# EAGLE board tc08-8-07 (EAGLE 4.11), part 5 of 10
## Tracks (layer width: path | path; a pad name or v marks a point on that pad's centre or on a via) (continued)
I/O_BAC_06  (via drill 0.61) (continued)
  Bottom 0.254: v354.37,76.5 349.29,76.5 348.97,76.82 348.33,76.82 348.02,76.5 v339.13,76.5 | v337.86,101.27 335.63,101.27 C03.R1 334.36,101.91 v330.87,101.91 | v344.52,233.99 v344.52,235.89 | v337.86,216.21 337.54,216.52 334.68,216.52 v334.36,216.84
I/O_BAC_07  (via drill 0.61)
  Top 0.254: D02.P1 350.56,35.55 350.56,39.68 349.6,40.63 349.6,46.34 348.97,46.98 348.97,54.92 349.29,55.23 349.29,73.33 350.87,74.92 v350.87,86.98 350.56,87.3 350.56,89.84 349.29,91.11 349.29,104.44 348.97,104.76 348.97,137.46 349.29,137.78 349.29,152.71 348.65,153.34 348.65,156.2 349.29,156.83 349.29,162.55 348.97,162.86 348.97,169.21 349.29,169.53 349.29,173.98 348.97,174.3 348.97,206.36 350.87,208.27 350.87,223.51 349.6,224.78 349.6,232.4 349.92,232.71 349.92,236.84 350.56,237.48 A02.P1
  Bottom 0.254: v350.87,86.98 337.22,86.98 335.63,88.57 C03.V1
I/O_BAC_08  (via drill 0.61)
  Top 0.254: v348.65,46.03 348.97,45.71 348.97,40.31 349.29,39.99 349.29,30.47 350.56,29.2 D02.S1 | v352.78,47.29 352.46,47.61 352.46,48.25 349.6,51.1 349.6,54.6 350.24,55.23 350.24,57.77 352.14,59.68 352.14,62.53 351.51,63.17 351.51,64.44 v354.37,67.3 | v353.41,231.45 352.78,230.81 352.78,225.09 v353.1,224.78 | v352.78,195.57 354.68,193.66 354.68,191.76 355.32,191.12 355.32,188.27 v354.68,187.63 | v363.89,185.73 362.3,184.14 362.3,166.68 364.21,164.77 v364.21,163.5
  Route2 0.254: v358.81,73.33 358.81,73.97 361.03,76.19 361.03,78.09 361.67,78.73 361.67,79.68 361.99,80 361.99,83.17 v363.57,84.76 | v353.1,224.78 353.1,224.14 352.14,223.19 352.14,218.11 350.87,216.84 350.87,208.27 349.6,207 349.6,205.73 354.37,200.96 352.46,199.06 352.46,195.89 v352.78,195.57 | v364.21,163.5 366.75,160.96 v345.16,139.37
  Route15 0.254: v364.21,94.6 361.67,97.14 361.67,97.78 356.59,102.86 356.59,103.49 333.73,126.35 333.73,127.94 332.14,129.53 C03.E2 332.14,130.8 333.09,131.75 333.09,132.39 332.46,133.02 337.54,138.1 v337.54,139.05 | v354.68,187.63 355,187.63 356.91,185.73 v360.08,185.73
  Bottom 0.254: v348.65,46.03 351.19,46.03 352.46,47.29 v352.78,47.29 | v354.37,67.3 356.27,65.39 357.86,65.39 359.45,66.98 359.45,68.88 358.81,69.52 v358.81,73.33 | v363.57,84.76 363.57,89.52 364.53,89.52 365.16,90.16 365.16,94.6 v364.21,94.6 | v353.41,231.45 351.51,231.45 A02.S1 | v363.89,185.73 v360.08,185.73 | v345.16,139.37 343.57,140.96 340.71,140.96 338.81,139.05 v337.54,139.05
I/O_BAC_09  (via drill 0.61)
  Top 0.254: v362.62,65.08 362.3,65.39 362.3,77.46 | 362.3,77.46 362.3,79.36 362.62,79.68 362.62,85.39 362.94,85.71 362.94,90.79 361.99,91.74 361.99,97.14 361.67,97.46 361.67,126.03 v361.99,126.35 | v332.14,126.03 332.14,124.45 C03.H2 | v348.97,265.1 v346.75,265.1 | v362.62,77.46 362.3,77.46
  Route2 0.254: v372.78,240.97 371.83,240.02 371.83,225.09 373.42,223.51 373.42,148.26 371.83,146.67 371.83,145.72 371.51,145.4 371.51,106.67 373.42,104.76 373.42,73.01 v371.83,71.43
  Bottom 0.254: v362.62,65.08 360.08,65.08 357.22,62.22 342.94,62.22 341.98,63.17 D02.D2 | v361.99,126.35 361.35,125.72 332.46,125.72 v332.14,126.03 | v346.75,265.1 346.43,265.42 342.94,265.42 341.98,266.37 A02.D2 | v348.97,265.1 358.49,265.1 361.03,262.56 362.62,262.56 363.26,261.93 366.43,261.93 366.75,262.24 367.38,262.24 371.83,257.8 371.83,240.97 v372.78,240.97 | v371.83,71.43 371.83,79.36 363.26,79.36 362.62,78.73 v362.62,77.46
I/O_BAC_10  (via drill 0.61)
  Top 0.254: v321.66,116.83 321.66,115.56 321.03,114.92 321.03,105.08 321.66,104.44 321.66,102.86 321.03,102.22 321.03,98.1 321.66,97.46 321.66,96.51 320.39,95.24 320.39,90.47 319.44,89.52 319.44,84.76 317.54,82.86 v317.54,76.5 | v321.03,59.04 v321.03,75.87 | v348.02,256.53 348.02,256.85 345.16,259.7 345.16,262.56 344.84,262.88 A02.E2 | v349.92,254.62 349.6,254.3 349.6,251.45 349.29,251.13 349.29,249.86 351.51,247.64 v351.51,246.68
  Route2 0.254: v349.92,254.62 v348.02,256.53 | v370.56,210.49 370.56,170.49 372.15,168.9 372.15,150.48 370.56,148.89 370.56,147.94 370.24,147.62 370.24,64.76 363.26,57.77 363.26,57.14 v362.62,56.5
  Route15 0.254: v351.51,246.68 351.51,245.73 355.32,241.92 355.32,229.22 361.67,222.87 361.67,219.38 362.62,218.43 362.62,217.79 369.61,210.81 370.24,210.81 v370.56,210.49
  Bottom 0.254: v321.66,116.83 322.3,116.19 330.24,116.19 331.19,117.14 C03.K2 | v317.54,76.5 318.17,75.87 v321.03,75.87 | v321.03,59.04 342.94,59.04 343.89,60 D02.E2 345.16,60 346.75,60 350.87,55.87 361.99,55.87 v362.62,56.5
I/O_BAC_11  (via drill 0.61)
  Top 0.254: v323.89,110.48 323.57,110.16 323.57,95.87 324.2,95.24 324.2,90.47 326.11,88.57 v326.11,84.76 | v360.72,86.03 361.99,84.76 361.99,80 361.67,79.68 v361.67,53.33 | v292.77,273.67 292.45,273.99 292.45,288.28 290.87,289.86 290.87,296.85 333.41,296.85 340.71,289.55 340.71,286.05 342.62,284.15 342.62,263.51 343.57,262.56 343.57,258.43 344.21,257.8 A02.H2 | v284.52,271.13 283.56,270.18 283.56,267.96 282.93,267.32 282.93,251.45 v283.25,251.13 | v264.83,250.18 263.88,249.23 263.88,245.73 264.51,245.1 264.51,242.56 263.24,241.29 v263.24,219.38 | v91.79,219.06 92.11,218.74 92.11,204.46 88.62,200.96 88.62,196.2 87.35,194.93 v87.35,193.34 | v85.76,189.85 85.44,189.54 85.44,158.1 85.13,157.79 85.13,156.52 85.44,156.2 85.44,35.55 92.11,28.88 v92.11,27.61 | v149.26,28.25 149.58,28.56 149.58,32.37 150.21,33.01 152.75,33.01 152.75,32.37 159.1,26.02 159.1,21.58 163.55,17.13 178.47,17.13 v178.47,19.35 | v181.96,22.85 v185.46,19.35 | v193.08,19.35 v196.25,22.53
  Route2 0.254: v143.86,27.29 145.13,27.29 146.72,25.71 v149.26,28.25 | v178.47,19.35 v181.96,22.85 | v254.99,10.46 262.61,2.84 262.93,3.16 290.87,3.16 291.5,3.8 292.45,3.8 341.03,52.38 342.62,52.38 343.89,53.64 D02.H2
  Route15 0.254: v277.85,255.58 276.9,255.58 v271.82,250.49 | v196.25,22.53 198.47,24.75 204.19,19.04 204.19,18.4 204.82,17.77 206.41,17.77 207.05,17.13 208,17.13 209.27,15.86 211.17,15.86 211.81,15.23 216.25,15.23 219.43,12.05 221.02,12.05 221.65,11.42 233.72,11.42 v234.03,11.1
  Bottom 0.254: v323.89,110.48 324.52,109.84 330.24,109.84 331.19,110.8 C03.M2 | v326.11,84.76 326.43,85.08 335.95,85.08 336.59,85.71 349.92,85.71 350.24,85.39 353.1,85.39 353.73,86.03 v360.72,86.03 | v361.67,53.33 361.03,52.69 349.6,52.69 348.65,53.64 345.16,53.64 D02.H2 | v292.77,273.67 292.77,272.4 291.82,272.4 290.55,271.13 v284.52,271.13 | v283.25,251.13 278.8,255.58 v277.85,255.58 | v271.82,250.49 270.86,249.54 265.47,249.54 v264.83,250.18 | v263.24,219.38 200.06,219.38 199.74,219.06 v91.79,219.06 | v87.35,193.34 85.76,191.76 v85.76,189.85 | v92.11,27.61 93.06,26.66 143.23,26.66 v143.86,27.29 | v185.46,19.35 187.04,17.77 191.49,17.77 v193.08,19.35 | v234.03,11.1 234.99,10.15 254.67,10.15 v254.99,10.46
I/O_BMB_00  (via drill 0.61)
  Top 0.254: v335.32,65.39 335.32,69.2 D03.B1 | v310.55,61.27 311.19,60.63 311.19,22.53 305.79,17.13 v305.79,12.05 | v112.43,11.42 110.84,13.01 110.84,172.39 v110.53,172.71 | v134.34,173.02 133.7,173.66 133.7,293.68 134.34,294.31 v134.34,294.94 | v232.13,296.22 236.89,291.45 v236.89,286.05 | v328.65,281.93 334.68,275.9 334.68,273.67 A03.B1 | v351.83,153.98 351.83,144.13 351.19,143.5 C02.A1 | v362.94,153.98 362.3,154.61 362.3,157.79 362.62,158.1 362.62,160.96 362.3,161.28 362.3,163.5 v362.94,164.14 | v360.4,207.63 v360.4,210.17 | v361.03,217.79 359.13,219.7 359.13,227.95 358.81,228.27 358.81,240.02 358.49,240.33 358.49,247.32 358.81,247.64 358.81,249.54 359.45,250.18 359.45,253.04 358.81,253.67 v358.81,277.8
  Bottom 0.254: v335.32,65.39 336.27,64.44 336.27,62.22 313.73,62.22 312.77,63.17 311.19,63.17 310.55,62.53 v310.55,61.27 | v305.79,12.05 305.47,12.37 292.77,12.37 292.14,11.74 272.45,11.74 272.13,11.42 257.85,11.42 255.94,9.51 234.35,9.51 232.45,11.42 221.33,11.42 220.7,10.78 115.29,10.78 114.65,11.42 v112.43,11.42 | v110.53,172.71 134.02,172.71 v134.34,173.02 | v134.34,294.94 134.66,294.63 145.45,294.63 145.77,294.31 173.07,294.31 173.71,294.94 203.87,294.94 204.19,294.63 205.46,294.63 207.68,296.85 231.49,296.85 v232.13,296.22 | v236.89,286.05 238.8,284.15 238.8,283.83 240.38,282.24 270.23,282.24 271.18,283.2 299.44,283.2 301.03,281.61 328.33,281.61 v328.65,281.93 354.68,281.93 v358.81,277.8 | v362.94,153.98 v351.83,153.98 | v362.94,164.14 368.02,169.21 368.02,205.09 362.94,205.09 v360.4,207.63 | v360.4,210.17 360.4,210.81 361.99,212.39 361.99,217.79 v361.03,217.79
I/O_BMB_01  (via drill 0.61)
  Top 0.254: v329.6,65.08 329.28,65.39 v329.28,68.25 | v331.19,70.16 333.09,72.06 v333.09,77.14 | v352.46,77.46 353.41,76.5 v353.41,73.97 | v357.86,71.43 360.08,71.43 v360.08,76.5 | v360.72,131.43 359.76,131.43 359.76,132.07 358.81,133.02 v358.81,140.32 | v348.33,138.1 348.02,137.78 348.02,133.97 C02.D1 | v346.75,263.19 349.6,260.34 349.6,256.53 v351.51,254.62 | v364.21,241.61 362.62,240.02 362.62,239.06 362.3,238.75 362.3,237.48 363.26,236.52 v363.89,236.52 | v365.48,197.47 365.8,197.15 365.8,192.08 v364.84,191.12
  Route2 0.254: v365.16,248.27 365.16,242.56 v364.21,241.61
  Route15 0.254: v364.21,108.25 364.21,108.57 362.3,110.48 362.3,113.02 v363.26,113.97 | v363.89,236.52 363.89,235.26 364.84,234.3 364.84,223.83 365.16,223.51 365.16,217.79 370.88,212.08 370.88,211.44 371.51,210.81 371.51,203.51 v365.48,197.47 | v364.84,191.12 364.84,184.46 365.16,184.14 365.16,182.23 365.48,181.92 365.48,164.45 365.8,164.14 365.8,151.43 367.38,149.85 367.38,138.1 v360.72,131.43
  Bottom 0.254: v329.6,65.08 333.09,65.08 334.36,63.81 D03.D1 | v331.19,70.16 v329.28,68.25 | v333.09,77.14 333.41,77.46 344.84,77.46 345.16,77.14 347.7,77.14 348.02,77.46 v352.46,77.46 | v353.41,73.97 355.95,71.43 v357.86,71.43 | v360.08,76.5 360.08,77.14 369.29,86.35 369.29,108.25 v364.21,108.25 | v363.26,113.97 364.53,115.24 365.16,115.24 368.97,119.05 368.97,131.43 v360.72,131.43 | v358.81,140.32 358.18,140.96 351.51,140.96 348.65,138.1 v348.33,138.1 | v346.75,263.19 345.16,264.78 341.35,264.78 340.4,265.74 336.27,265.74 335.63,266.37 A03.D1 | v351.51,254.62 353.73,252.4 357.54,252.4 358.81,251.13 358.81,246.37 359.76,246.37 360.08,246.05 362.3,246.05 364.53,248.27 v365.16,248.27
I/O_BMB_02  (via drill 0.61)
  Top 0.254: v339.13,65.08 338.17,64.12 D03.E1 | v353.1,96.83 354.05,97.78 354.05,99.68 352.78,100.95 352.78,102.22 353.41,102.86 v353.41,105.08 | v337.86,266.69 337.86,264.15 A03.E1 | v314.36,270.81 v314.36,266.37 | v303.88,271.13 302.61,269.86 302.61,268.91 v301.03,267.32 | v289.91,263.19 288.96,262.24 288.96,259.38 v289.28,259.07
  Route2 0.254: v339.13,65.08 339.13,65.71 339.76,66.35 339.76,70.79 341.03,72.06 341.03,80.63 341.35,80.95 341.35,85.08 344.21,87.94 | 344.21,87.94 v353.1,96.83 | v347.06,111.75 353.1,117.78 353.73,117.78 v354.37,118.41 | v289.28,259.07 289.28,255.89 287.06,253.67 287.06,252.4 v274.67,240.02 | v268.96,241.29 267.69,241.29 242.61,216.21 241.34,216.21 238.16,213.03 238.16,206.36 237.84,206.05 237.84,205.41 234.99,202.55 234.99,201.28 234.67,200.96 234.67,195.57 232.45,193.34 232.45,192.71 229.59,189.85 229.59,188.58 228.95,187.95 228.95,184.77 228.64,184.46 228.64,183.82 227.05,182.23 226.73,182.23 225.14,180.64 225.14,180.33 223.24,178.42 223.24,177.15 v222.29,176.2 | v259.12,129.53 259.12,131.43 261.34,133.65 261.97,133.65 264.51,131.11 264.51,130.48 v264.2,130.16 | v324.2,88.89 329.28,83.81 333.09,87.62 338.17,87.62 340.71,90.16 341.98,90.16 344.21,87.94
  Route15 0.254: v353.41,105.08 353.41,105.4 v347.06,111.75 | v354.37,118.41 349.6,123.18 349.6,124.77 348.02,126.35 C02.F1 | v219.75,174.3 217.84,172.39 220.06,170.17 220.7,170.17 221.97,168.9 221.97,166.68 222.6,166.04 222.6,164.77 224.19,163.18 224.51,163.18 225.14,162.55 225.14,157.47 228,154.61 229.27,154.61 229.59,154.29 234.35,154.29 241.65,146.99 243.24,146.99 250.54,139.69 250.54,138.42 259.12,129.84 v259.12,129.53 | v264.2,130.16 264.2,129.84 266.42,127.62 266.42,125.08 265.15,123.81 v270.23,118.73 | v274.67,119.69 276.26,119.69 288.33,107.62 288.33,105.72 288.64,105.4 288.64,101.59 v297.85,92.38 | v306.11,90.47 306.74,90.47 314.68,98.41 v324.2,88.89
  Bottom 0.254: v337.86,266.69 336.59,267.96 321.35,267.96 318.81,265.42 315.31,265.42 v314.36,266.37 | v314.36,270.81 311.19,273.99 310.55,273.99 309.92,274.62 307.69,274.62 304.2,271.13 v303.88,271.13 | v301.03,267.32 298.49,264.78 291.5,264.78 v289.91,263.19 | v274.67,240.02 270.23,240.02 v268.96,241.29 | v222.29,176.2 220.38,174.3 v219.75,174.3 | v270.23,118.73 270.86,119.37 274.36,119.37 v274.67,119.69 | v297.85,92.38 300.07,90.16 305.79,90.16 v306.11,90.47
I/O_BMB_03  (via drill 0.61)
  Top 0.254: 334.68,115.88 v335.32,116.51 | 334.68,115.88 333.41,114.61 333.41,88.57 334.36,87.62 334.36,72.38 333.41,71.43 333.41,56.82 334.36,55.87 334.36,51.74 334.68,51.42 D03.J1 | 333.41,132.07 333.41,123.81 333.09,123.49 333.09,117.46 334.68,115.88 | 333.41,132.07 333.41,154.29 333.09,154.61 333.09,179.06 333.41,179.37 333.41,203.51 335,205.09 335,214.93 333.41,216.52 333.41,238.43 332.78,239.06 332.78,241.92 333.09,242.24 333.09,251.77 334.68,253.35 A03.J1 | 333.41,132.07 v330.87,132.07
  Bottom 0.254: C05.D2 303.88,133.65 304.2,133.97 308.33,133.97 308.96,134.61 311.19,134.61 312.14,133.65 315.31,133.65 C04.D2 316.58,133.02 317.54,132.07 322.93,132.07 323.25,132.39 327.7,132.39 328.01,132.07 v330.87,132.07 | v335.32,116.51 337.86,119.05 342.94,119.05 344.21,120.32 347.06,120.32 C02.J1
I/O_BMB_03\  (via drill 0.61)
  Top 0.254: v339.13,62.53 339.44,62.22 339.44,59.68 339.13,59.36 339.13,55.23 338.49,54.6 D03.H1 | v339.13,267.32 339.44,267 339.44,261.29 338.49,260.34 338.49,257.8 A03.H1
  Route15 0.254: v354.37,66.03 355.95,66.03 356.59,65.39 358.81,65.39 360.72,67.3 361.03,67.3 373.42,79.68 373.42,115.24 v372.46,116.19 | v372.46,145.08 372.46,145.4 371.83,146.04 371.83,148.26 373.42,149.85 373.42,237.8 371.83,239.38 371.83,241.29 v372.78,242.24
  Bottom 0.254: v339.13,62.53 339.13,64.12 340.08,64.12 341.03,65.08 351.83,65.08 352.78,66.03 v354.37,66.03 | v372.46,145.08 v372.46,116.19 | v372.78,242.24 372.78,265.1 359.45,265.1 356.91,267.64 355,267.64 354.68,267.96 351.83,267.96 351.51,267.64 348.65,267.64 348.33,267.96 345.48,267.96 345.16,267.64 342.3,267.64 341.98,267.96 339.76,267.96 v339.13,267.32
I/O_BMB_04  (via drill 0.61)
  Top 0.254: v364.84,42.53 365.16,42.85 365.16,74.28 364.84,74.6 364.84,76.5 365.16,76.82 365.16,112.07 v364.84,112.38 | v366.75,242.56 366.43,242.24 366.43,203.19 367.38,202.24 367.38,201.6 367.07,201.28 367.07,145.4 366.43,144.77 366.43,113.33 v366.75,113.02 | v320.71,115.88 320.39,116.19 320.39,128.58 319.44,129.53 C04.E2
  Bottom 0.254: C05.E2 307.06,130.48 307.38,130.8 311.5,130.8 312.14,131.43 316.27,131.43 317.22,130.48 318.49,130.48 C04.E2 | v364.84,42.53 343.89,42.53 343.57,42.21 339.44,42.21 338.81,41.58 D03.M1 | v366.75,242.56 362.62,242.56 362.3,242.87 340.08,242.87 338.81,244.14 A03.M1 | v366.75,113.02 366.43,112.7 365.16,112.7 v364.84,112.38 352.14,112.38 350.56,113.97 348.33,113.97 C02.L1 347.7,114.92 346.11,116.51 345.48,116.51 345.16,116.19 336.27,116.19 335.63,115.56 321.03,115.56 v320.71,115.88
I/O_BMB_04\  (via drill 0.61)
  Top 0.254: v306.11,254.94 307.69,256.53 v307.69,261.93 | v331.19,258.75 333.09,258.75 333.09,254.62 v332.78,254.3 | v337.54,253.35 336.59,252.4 336.59,249.54 337.22,248.91 v337.22,247.96
  Route2 0.254: v283.88,73.65 283.88,73.97 284.83,74.92 284.83,78.73 281.34,82.22 281.66,82.54 281.66,90.79 282.29,91.43 282.29,95.24 288.33,101.27 288.33,103.81 291.82,107.3 291.82,109.84 292.14,110.16 292.14,119.37 299.76,126.99 v299.76,127.3 | v287.69,157.15 291.5,157.15 v296.26,161.91 | v285.15,186.04 288.01,186.04 298.17,196.2 298.17,207.63 284.83,220.97 285.47,221.6 285.47,225.41 v287.37,227.32
  Route15 0.254: v332.14,46.03 333.41,44.75 334.36,44.75 D03.L1 | v306.11,46.03 303.57,46.03 287.37,62.22 287.06,62.22 286.42,62.85 286.42,64.44 284.83,66.03 284.83,67.3 282.93,69.2 282.93,72.69 v283.88,73.65 | v299.76,127.3 292.77,134.29 292.77,135.56 292.14,136.2 292.14,145.72 289.28,148.58 289.28,150.17 287.37,152.07 287.37,153.66 286.1,154.93 286.1,156.2 287.37,157.47 v287.69,157.15 | v296.26,161.91 296.26,163.82 292.45,167.63 292.45,168.26 291.18,169.53 290.55,169.53 289.28,170.8 289.28,182.55 287.06,184.77 286.42,184.77 v285.15,186.04 | v287.69,230.18 289.6,232.08 289.28,232.4 289.28,233.35 v287.37,235.26 | v304.52,249.54 304.52,253.35 v306.11,254.94
  Bottom 0.254: v332.14,46.03 333.09,46.98 333.09,49.2 327.7,49.2 326.74,50.15 326.11,50.15 319.76,43.8 317.22,43.8 316.27,42.85 314.04,42.85 310.87,46.03 v306.11,46.03 | v287.37,227.32 287.37,230.18 v287.69,230.18 | v287.37,235.26 296.26,244.14 296.58,244.14 299.12,246.68 299.12,248.59 302.3,248.59 303.25,249.54 v304.52,249.54 | v307.69,261.93 312.46,261.93 315.63,258.75 v331.19,258.75 | v332.78,254.3 334.36,252.72 335.63,252.72 336.27,253.35 v337.54,253.35 | v337.22,247.96 335.63,247.96 A03.L1
I/O_BMB_05  (via drill 0.61)
  Top 0.254: v363.26,30.15 365.8,32.69 365.8,60.31 367.07,61.58 367.07,62.22 366.43,62.85 366.43,73.33 367.38,74.28 367.38,75.55 367.07,75.87 367.07,99.05 367.7,99.68 v367.7,106.35 368.02,106.67 368.02,109.52 368.34,109.84 368.34,122.22 367.7,122.86 367.7,125.08 | v368.02,227.95 367.7,227.64 367.7,203.82 368.65,202.87 368.65,200.96 368.34,200.65 368.34,144.77 367.7,144.13 367.7,125.08 | 367.7,125.08 v368.02,125.08 | v315.95,124.77 C04.F2
  Bottom 0.254: C05.F2 306.74,126.99 308.01,128.26 314.36,128.26 315.31,127.3 C04.F2 | v363.26,30.15 344.21,30.15 343.57,29.51 339.44,29.51 338.81,28.88 D03.S1 | v367.7,106.35 367.38,106.03 352.14,106.03 350.56,107.62 348.33,107.62 C02.N1 | v368.02,227.95 365.48,230.49 339.76,230.49 338.81,231.45 A03.S1 | v315.95,124.77 316.27,125.08 v368.02,125.08
I/O_BMB_05\
  Top 0.254: D03.P1 337.86,35.55 336.9,36.5 336.9,46.98 336.59,47.29 336.59,48.88 336.9,49.2 336.9,66.03 336.59,66.35 336.59,81.27 336.27,81.58 336.27,87.3 336.9,87.94 336.9,132.07 336.59,132.39 336.59,179.37 336.27,179.69 336.27,218.74 336.9,219.38 336.9,236.52 337.86,237.48 A03.P1
I/O_BMB_06  (via drill 0.61)
  Top 0.254: v366.11,61.9 365.8,62.22 365.8,73.65 366.75,74.6 366.75,75.24 366.43,75.55 366.43,99.68 v366.75,100 366.75,109.21 367.7,110.16 367.7,113.33 367.07,113.97 367.07,121.91 | v367.38,255.26 367.07,254.94 367.07,243.51 367.7,242.87 367.7,242.24 367.07,241.61 367.07,203.51 368.02,202.55 368.02,201.28 367.7,200.96 367.7,145.08 367.07,144.45 367.07,121.91 | 367.07,121.91 v367.38,121.91
  Bottom 0.254: C05.H2 310.87,123.81 312.14,125.08 314.36,125.08 315.63,123.81 C04.H2 319.76,123.49 320.71,122.54 339.44,122.54 339.76,122.86 342.62,122.86 343.57,121.91 v367.38,121.91 | v366.11,61.9 365.8,61.58 333.41,61.58 332.46,60.63 D03.E2 | v366.75,100 366.43,100.32 351.51,100.32 350.56,101.27 348.33,101.27 C02.R1 | v367.38,255.26 360.72,261.93 333.73,261.93 332.46,263.19 A03.E2
I/O_BMB_06\  (via drill 0.61)
  Top 0.254: v327.38,55.87 327.06,56.18 327.06,57.46 327.7,58.09 327.7,62.22 328.33,62.85 D03.D2 | v335.32,53.01 336.27,52.06 336.27,49.52 335.95,49.2 335.95,45.39 336.27,45.07 336.27,41.26 333.41,38.4 333.41,36.82 333.73,36.5 333.73,32.37 330.55,29.2 330.55,24.12 v319.76,13.32 | v268.32,8.56 264.83,12.05 v264.83,15.54 | v261.34,15.54 260.07,16.82 v260.07,23.48 | v249.59,25.07 248.64,26.02 248.64,27.29 244.83,31.1 244.83,41.26 242.92,43.17 v242.92,43.8 | v216.89,69.52 216.57,69.84 216.57,72.06 215.94,72.69 215.94,74.28 216.57,74.92 v216.57,77.77 | v173.39,89.21 171.49,91.11 171.49,98.1 168.63,100.95 168.63,108.89 170.53,110.8 170.53,113.02 171.17,113.65 171.17,117.46 168.63,120 168.63,131.43 165.45,134.61 165.45,135.88 165.14,136.2 165.14,138.42 166.72,140.01 166.72,140.96 168.31,142.55 168.31,143.18 v166.72,144.77 | v173.07,151.12 174.34,152.39 174.34,158.1 171.8,160.64 171.8,164.14 172.44,164.77 172.44,166.99 171.8,167.63 171.8,168.9 172.44,169.53 v172.44,171.76 | v189.9,215.57 190.22,215.89 190.22,236.52 188.95,237.8 v188.95,238.43
  Route2 0.254: v255.62,23.8 250.86,23.8 v249.59,25.07 | v205.78,88.57 v216.57,77.77 | v166.72,144.77 v173.07,151.12 | v172.44,171.76 172.44,172.07 174.34,173.98 174.34,178.42 174.66,178.74 174.66,186.99 180.69,193.03 180.69,198.43 184.5,202.24 184.5,207.63 185.77,208.9 185.77,211.12 189.9,215.25 v189.9,215.57 | v192.44,266.37 193.08,266.37 194.66,267.96 198.79,267.96 204.82,273.99 205.78,273.99 209.27,277.48 214.98,277.48 216.57,279.07 219.75,279.07 228.95,288.28 234.03,288.28 236.57,290.82 238.8,290.82 239.43,291.45 269.28,291.45 269.91,292.09 281.66,292.09 316.9,256.85 318.49,258.43 321.98,258.43 322.3,258.75 327.06,258.75 331.19,254.62 333.09,256.53 333.09,260.34 328.01,265.42 328.65,266.05 A03.D2
  Route15 0.254: v242.92,43.8 236.89,49.83 236.57,49.83 v216.89,69.52 | v188.95,238.43 188.95,239.38 178.79,249.54 178.15,249.54 176.88,250.81 176.88,251.45 188,262.56 188.63,262.56 v192.44,266.37
  Bottom 0.254: v327.38,55.87 327.7,55.55 332.78,55.55 v335.32,53.01 | v319.76,13.32 315.31,8.88 296.9,8.88 295.95,7.93 276.9,7.93 276.26,8.56 270.23,8.56 269.91,8.88 268.64,8.88 v268.32,8.56 | v261.34,15.54 v264.83,15.54 | v260.07,23.48 259.75,23.8 v255.62,23.8 | v205.78,88.57 205.46,88.89 203.55,88.89 202.28,87.62 174.98,87.62 v173.39,89.21
I/O_BMB_07  (via drill 0.61)
  Top 0.254: v326.43,49.2 324.2,51.42 324.2,66.03 323.57,66.66 323.57,71.11 323.25,71.43 v323.25,75.55 | v348.65,75.87 348.33,76.19 348.33,88.57 C02.V1 | v368.02,244.46 368.34,244.14 368.34,241.92 368.02,241.61 368.02,229.22 368.97,228.27 368.97,227.64 368.34,227 368.34,204.14 369.29,203.19 369.29,200.65 368.97,200.33 368.97,144.45 368.34,143.81 368.34,126.03 368.97,125.4 v368.97,109.21 368.97,108.89 368.65,108.57 368.65,106.03 368.34,105.72 368.34,99.36 367.7,98.73 367.7,76.5 v368.02,76.19 | v316.58,115.88 316.58,119.69 316.27,120 C04.J2
  Bottom 0.254: C05.J2 303.88,120.96 304.84,121.91 311.19,121.91 312.14,120.96 315.31,120.96 C04.J2 | v326.43,49.2 327.06,48.57 330.55,48.57 331.19,47.93 D03.K2 | v323.25,75.55 348.33,75.55 v348.65,75.87 348.97,75.55 360.4,75.55 360.72,75.87 367.7,75.87 v368.02,76.19 | v368.02,244.46 366.75,245.73 362.94,245.73 362.62,245.42 359.76,245.42 359.45,245.73 346.75,245.73 346.43,246.05 341.03,246.05 338.17,248.91 334.05,248.91 332.46,250.49 A03.K2 | v316.58,115.88 319.44,113.02 332.78,113.02 336.59,109.21 v368.97,109.21
I/O_BMB_07\  (via drill 0.61)
  Top 0.254: v332.14,51.1 332.14,53.33 D03.H2 | v337.86,43.8 v337.86,45.71 | v340.71,40.95 342.94,38.72 342.94,18.72 v337.54,13.32 | v300.07,7.93 295.63,7.93 v295.63,8.88 | v279.75,9.51 279.44,9.83 v279.44,18.72 | v281.02,23.8 279.75,25.07 279.75,29.83 v280.07,30.15 | v218.16,76.19 v221.02,73.33 | v182.92,81.9 181.65,83.17 181.65,87.94 181.33,88.25 181.33,90.47 v182.6,91.74
  Route2 0.254: v340.71,40.95 v337.86,43.8 | v144.5,130.48 142.59,132.39 143.23,133.02 143.23,157.79 134.97,166.04 136.24,167.31 136.24,191.44 139.74,194.93 139.74,227.95 175.93,264.15 177.2,264.15 188,274.94 188.95,274.94 191.81,277.8 197.2,277.8 197.52,278.12 202.28,278.12 203.24,279.07 213.4,279.07 231.49,297.17 281.02,297.17 319.12,259.07 321.98,261.93 325.16,261.93 330.55,256.53 331.19,257.16 A03.H2
  Route15 0.254: v268.64,30.78 266.42,28.56 253.4,41.58 253.4,41.9 252.13,43.17 251.81,43.17 246.73,48.25 246.1,48.25 231.18,63.17 230.86,63.17 221.97,72.06 221.97,72.38 v221.02,73.33 | v208.32,75.24 206.41,73.33 205.14,74.6 204.51,74.6 200.06,79.05 199.11,79.05 v198.47,79.68 | v182.6,91.74 182.28,91.74 v150.21,123.81
  Bottom 0.254: v332.14,51.1 334.05,49.2 334.05,46.34 337.22,46.34 v337.86,45.71 | v337.54,13.32 332.46,8.24 300.39,8.24 v300.07,7.93 | v295.63,8.88 295.31,8.56 280.71,8.56 v279.75,9.51 | v279.44,18.72 282.29,21.58 282.29,23.8 v281.02,23.8 | v280.07,30.15 279.75,30.47 268.96,30.47 v268.64,30.78 | v218.16,76.19 209.59,76.19 208.63,75.24 v208.32,75.24 | v198.47,79.68 196.25,81.9 v182.92,81.9 | v150.21,123.81 151.48,123.81 152.12,124.45 152.12,125.72 149.26,125.72 v144.5,130.48
I/O_BMB_08  (via drill 0.61)
  Top 0.254: v307.06,112.7 307.06,116.51 306.74,116.83 C05.K2 | v332.46,108.25 330.55,110.16 330.55,126.03 v331.82,127.3 | v333.41,86.66 332.46,85.71 332.46,81.27 332.78,80.95 332.78,78.09 330.24,75.55 330.24,66.35 330.55,66.03 330.55,64.76 330.24,64.44 330.24,36.82 331.51,35.55 D03.P2 | v332.14,210.81 331.82,211.12 331.82,222.24 330.24,223.83 330.24,232.08 330.87,232.71 330.87,236.84 331.51,237.48 A03.P2 | v332.14,178.74 330.55,177.15 v330.55,172.71 | v343.89,147.62 343.57,147.31 343.57,143.81 342.94,143.18 342.94,140.96 343.25,140.64 343.25,137.15 342.94,136.83 342.94,136.2 344.84,134.29 344.84,130.8 C02.E2
  Route2 0.254: v338.17,191.12 338.17,189.22 336.9,187.95 336.9,183.5 v332.14,178.74
  Route15 0.254: v328.65,112.07 v332.46,108.25 336.9,103.81 336.9,97.78 344.52,90.16 337.54,83.17 336.9,83.17 v333.41,86.66 | v332.14,210.81 332.14,207.95 336.27,203.82 336.27,200.01 339.13,197.15 339.44,197.15 340.08,196.52 340.08,196.2 v341.03,195.25 | v330.55,172.71 330.55,170.49 326.43,166.36 327.38,165.4 327.38,164.14 v343.89,147.62
  Bottom 0.254: v307.06,112.7 307.38,112.38 328.33,112.38 v328.65,112.07 | v331.82,127.3 332.78,128.26 339.44,128.26 341.03,129.84 343.89,129.84 C02.E2 | v341.03,195.25 341.03,193.66 338.49,191.12 v338.17,191.12
I/O_BMB_08\  (via drill 0.61)
  Top 0.254: v333.41,53.01 333.09,52.69 333.09,42.85 332.14,41.9 D03.M2 | v319.76,55.55 320.08,55.87 320.08,59.36 320.39,59.68 320.39,64.76 v320.08,65.08 | v321.98,67.93 v321.98,65.39 | v310.87,68.57 311.19,68.88 311.19,71.74 310.55,72.38 310.55,74.92 311.19,75.55 311.19,82.86 303.57,90.47 v303.57,91.43 | v285.79,171.12 284.52,169.85 v284.52,167.95
  Route2 0.254: v303.57,91.43 303.57,92.06 319.44,107.94 319.44,109.52 320.39,110.48 320.39,113.33 317.85,115.88 318.81,116.83 C04.K2 | v319.12,240.65 311.19,232.71 309.28,232.71 305.79,229.22 305.47,229.22 304.52,228.27 304.52,227.95 303.88,227.32 303.57,227.32 302.93,226.68 302.93,224.78 292.77,214.62 v292.77,214.3 | v296.58,185.73 295.63,184.77 295.63,184.14 293.72,182.23 293.09,182.23 289.28,178.42 289.28,174.61 v285.79,171.12
  Route15 0.254: v328.65,244.46 324.84,240.65 v324.84,240.33 | v277.53,211.44 277.53,210.81 278.48,209.86 278.48,207.63 v277.85,207 | v283.88,200.33 283.88,199.06 289.91,193.03 289.91,192.71 290.87,191.76 291.18,191.76 293.09,189.85 293.09,189.54 294.04,188.58 294.36,188.58 294.99,187.95 294.99,187.31 v296.58,185.73 | v284.52,167.95 281.66,165.09 281.66,163.18 282.29,162.55 282.29,144.45 288.01,138.74 288.01,137.78 288.64,137.15 288.64,118.1 291.82,114.92 291.82,111.11 292.14,110.8 292.14,109.21 292.45,108.89 292.45,104.13 300.07,96.51 300.39,96.51 301.03,95.87 301.03,93.97 v303.57,91.43
  Bottom 0.254: v333.41,53.01 333.09,52.69 330.87,52.69 328.65,54.92 326.43,54.92 325.79,55.55 v319.76,55.55 | v320.08,65.08 320.39,65.39 v321.98,65.39 | v321.98,67.93 321.35,68.57 v310.87,68.57 | v324.84,240.33 324.2,239.7 320.71,239.7 319.76,240.65 v319.12,240.65 | v292.77,214.3 292.14,213.67 279.75,213.67 v277.53,211.44 | v277.85,207 283.88,200.96 v283.88,200.33 | v328.65,244.46 A03.M2
I/O_BMB_09  (via drill 0.61)
  Top 0.254: v336.27,28.56 336.9,27.93 v336.9,20.94 | v345.48,23.8 345.79,24.12 345.79,55.23 345.48,55.55 345.48,59.36 345.79,59.68 345.79,62.22 v343.89,64.12 | v348.65,73.97 350.24,75.55 350.24,83.17 v349.92,83.49 | v337.22,218.11 336.9,217.79 336.9,203.51 v338.17,202.24 | v360.08,173.02 v360.08,176.2 | v343.89,133.97 343.25,133.34 343.25,128.58 344.52,127.3 C02.H2 | v331.82,227.64 A03.S2
  Route2 0.254: v343.89,64.12 346.11,66.35 346.11,68.88 346.43,69.2 346.43,71.74 v348.65,73.97 | v360.08,173.02 359.13,172.07 359.13,169.21 358.81,168.9 358.81,159.69 356.59,157.47 356.59,156.83 352.78,153.02 352.78,149.85 349.92,146.99 349.92,145.4 344.21,139.69 344.21,138.74 346.43,136.51 v343.89,133.97
  Route15 0.254: v353.73,87.3 v349.92,83.49 | v364.21,95.87 362.3,97.78 362.3,102.22 356.59,107.94 356.59,109.84 346.43,120 346.43,121.59 344.84,123.18 C02.H2 | v331.82,227.64 331.82,227.32 333.41,225.73 333.41,221.92 v337.22,218.11 | v338.17,202.24 338.17,201.92 342.62,197.47 342.62,193.66 v360.08,176.2
  Bottom 0.254: v336.9,20.94 341.35,20.94 344.21,23.8 v345.48,23.8 | v353.73,87.3 354.05,87.62 355,87.62 360.4,93.02 361.35,93.02 v364.21,95.87 | v336.27,28.56 D03.S2
I/O_BMB_10  (via drill 0.61)
  Top 0.254: v335,47.61 333.73,46.34 333.73,41.26 332.78,40.31 332.78,36.5 333.09,36.18 333.09,34.28 329.92,31.1 329.92,26.98 328.97,26.02 D03.T2 | v350.87,51.1 352.14,52.38 352.14,55.87 v351.19,56.82 | v339.76,73.97 340.08,74.28 340.08,80.32 339.44,80.95 339.44,83.81 v339.76,84.13
  Route2 0.254: v346.11,84.13 346.11,85.39 355.32,94.6 355.32,99.68 358.49,102.86 358.49,110.48 361.67,113.65 361.67,117.14 v360.72,118.1 355.95,122.86 355.64,122.54 352.78,122.54 350.24,120 349.6,120 v347.06,117.46 | v338.81,242.87 327.7,231.76 328.97,230.49 328.97,229.22 A03.T2
  Route15 0.254: v348.33,59.68 351.19,62.53 v339.76,73.97 | v338.81,242.87 343.25,242.87 v350.87,235.26 | v357.86,234.3 363.57,240.02 364.84,238.75 364.84,235.26 365.48,234.62 365.48,224.14 365.8,223.83 365.8,218.11 371.51,212.39 371.51,211.76 372.15,211.12 372.15,150.48 368.02,146.36 368.02,126.35 368.97,125.4 368.97,124.77 364.53,120.32 364.53,120 363.26,118.73 361.35,118.73 v360.72,118.1
  Bottom 0.254: v335,47.61 336.59,49.2 348.97,49.2 v350.87,51.1 | v348.33,59.68 v351.19,56.82 | v346.11,84.13 v339.76,84.13 | v347.06,117.46 C02.K2 | v350.87,235.26 352.46,233.67 357.22,233.67 v357.86,234.3
I/O_BMB_11  (via drill 0.61)
  Top 0.254: v368.65,56.5 368.97,56.18 368.97,45.39 367.38,43.8 367.38,42.85 367.7,42.53 367.7,12.37 335.63,12.37 329.28,18.72 D03.V2 328.97,19.67 328.97,21.26 333.09,25.39 333.09,29.83 v333.73,30.47 | v364.21,57.46 362.3,59.36 362.3,63.17 v363.89,64.76 | v364.21,68.25 363.89,68.57 v363.89,71.43 | v357.54,86.98 355.95,88.57 355.95,95.87 v356.27,96.19 | v345.16,107.3 344.84,107.62 344.84,110.48 C02.M2 | v328.01,226.05 328.01,223.19 328.33,222.87 A03.V2 | v293.09,242.24 v294.36,240.97 | v258.8,206.68 257.21,206.68 255.94,207.95 252.13,207.95 252.13,205.41 254.04,203.51 v254.04,202.87 | v207.36,156.2 206.73,155.56 206.73,147.94 207.68,146.99 v207.68,145.72
  Route2 0.254: v283.88,238.11 283.88,237.8 275.94,229.86 275.94,228.59 268.96,221.6 268.96,219.38 263.24,213.67 263.24,212.39 261.34,210.49 261.34,209.22 v258.8,206.68 | v254.04,202.87 248.32,197.15 248,197.15 247.37,196.52 247.37,193.98 243.24,189.85 243.24,189.54 221.33,167.63 219.75,167.63 214.35,162.23 213.4,162.23 v207.36,156.2
  Route15 0.254: v363.89,71.43 367.7,75.24 367.07,75.87 367.07,79.68 v363.57,83.17 | v353.1,99.36 353.1,100.63 348.65,105.08 347.38,105.08 v345.16,107.3 | v328.01,226.05 328.01,226.36 v312.77,241.61 | v207.68,145.72 207.68,144.45 224.83,127.3 224.83,125.08 228.32,121.59 228.32,116.19 231.18,113.33 231.18,112.07 231.49,111.75 231.49,102.54 232.13,101.91 232.13,100.63 234.35,98.41 234.35,97.14 235.62,95.87 235.62,94.92 241.02,89.52 241.02,86.35 242.29,85.08 242.29,84.13 249.27,77.14 249.27,74.92 250.54,73.65 250.54,67.61 260.7,57.46 261.66,57.46 v280.07,39.04 | v287.37,32.37 v289.28,30.47
  Bottom 0.254: v368.65,56.5 367.7,57.46 v364.21,57.46 | v363.89,64.76 364.84,65.71 364.84,68.25 v364.21,68.25 | v363.57,83.17 361.67,85.08 361.67,86.98 v357.54,86.98 | v356.27,96.19 v353.1,99.36 | v312.77,241.61 308.96,245.42 307.38,245.42 307.06,245.73 299.12,245.73 v294.36,240.97 | v293.09,242.24 292.14,241.29 292.14,240.97 290.55,239.38 285.15,239.38 v283.88,238.11 | v280.07,39.04 286.74,32.37 v287.37,32.37 | v289.28,30.47 289.6,30.15 304.52,30.15 310.87,36.5 314.04,36.5 320.39,30.15 330.55,30.15 330.87,30.47 v333.73,30.47
I/O_BRK_RQ\  (via drill 0.61)
  Top 0.254: v368.02,52.06 367.7,52.38 367.7,59.36 368.97,60.63 368.97,73.01 370.24,74.28 370.24,94.6 369.61,95.24 369.61,97.78 371.19,99.36 371.19,113.97 370.88,114.29 370.88,148.26 372.46,149.85 v372.46,213.67 | v306.42,223.51 304.84,225.09 304.84,230.49 304.52,230.81 304.52,234.3 305.15,234.94 305.15,247 306.42,248.27 A05.K2 | v315.63,198.43 v315.63,201.28 | v312.77,203.51 311.5,204.77 311.5,207.31 311.82,207.63 v311.82,221.29
  Bottom 0.254: v368.02,52.06 349.29,52.06 348.97,52.38 341.03,52.38 340.71,52.06 330.55,52.06 330.24,52.38 327.38,52.38 324.2,49.2 308.33,49.2 307.06,47.93 D05.K2 | v372.46,213.67 372.46,221.29 364.84,221.29 364.53,220.97 311.82,220.97 | 311.82,220.97 308.96,220.97 v306.42,223.51 | v315.63,198.43 311.5,198.43 310.23,197.15 B05.D1 | v315.63,201.28 313.41,203.51 v312.77,203.51 | v311.82,221.29 311.82,220.97
I/O_BWC0\  (via drill 0.61)
  Top 0.254: 291.82,163.82 291.82,173.34 292.14,173.66 292.14,206.68 293.72,208.27 293.72,222.55 292.14,224.14 292.14,232.4 293.41,233.67 293.41,237.48 A06.P2 | 291.82,163.82 291.82,151.75 291.5,151.43 291.5,142.23 291.82,141.91 291.82,129.21 292.14,128.89 292.14,93.97 292.45,93.65 292.45,90.47 293.72,89.21 293.72,74.92 292.14,73.33 292.14,56.82 291.82,56.5 291.82,53.01 292.14,52.69 292.14,36.82 293.41,35.55 D06.P2 | v363.26,132.39 362.94,132.7 362.94,135.24 362.3,135.88 362.3,144.45 364.84,146.99 v364.84,148.26 | v348.33,149.21 347.7,148.58 v347.7,146.67 | v325.47,147.62 324.84,148.26 v324.84,151.75 | v292.14,163.82 291.82,163.82
  Route2 0.254: v363.26,132.39 361.67,130.8 361.67,129.84 360.72,128.89 360.72,127.62 C01.F1
  Route15 0.254: v324.84,151.75 313.09,163.5 v312.77,163.5
  Bottom 0.254: v364.84,148.26 359.76,148.26 358.81,149.21 v348.33,149.21 | v347.7,146.67 342.94,146.67 341.67,147.94 325.79,147.94 v325.47,147.62 | v312.77,163.5 312.46,163.82 v292.14,163.82
I/O_DATA_IN  (via drill 0.61)
  Top 0.254: v371.19,44.75 370.88,45.07 370.88,72.06 372.15,73.33 372.15,95.55 371.51,96.19 371.51,96.83 373.42,98.73 373.42,145.72 v372.78,146.36 | v361.99,149.21 361.67,149.53 361.67,158.1 361.99,158.42 361.99,160.64 361.67,160.96 v361.67,193.03 | v362.3,196.52 361.99,196.84 361.99,207 362.62,207.63 362.62,224.46 362.3,224.78 362.3,226.05 362.62,226.36 362.62,230.81 362.3,231.13 362.3,232.4 362.62,232.71 v362.62,233.99 | v310.23,187.63 310.87,188.27 310.87,193.66 308.33,196.2 v308.33,198.11 | v304.84,198.11 304.84,200.96 307.69,203.82 307.69,205.09 v308.33,205.73 | v314.36,206.05 314.04,206.36 314.04,229.86 v313.73,230.18
  Route2 0.254: v305.79,183.5 306.11,183.5 v310.23,187.63
  Bottom 0.254: v371.19,44.75 362.94,36.5 328.33,36.5 325.16,39.68 312.46,39.68 311.5,40.63 307.38,40.63 307.06,40.95 D05.M2 | v372.78,146.36 369.92,149.21 v361.99,149.21 | v361.67,193.03 361.67,196.2 361.99,196.2 v362.3,196.52 | v362.62,233.99 362.62,235.57 361.67,235.57 361.03,236.21 348.33,236.21 347.7,236.84 322.3,236.84 321.98,237.16 | 321.98,237.16 319.44,239.7 313.09,239.7 308.65,244.14 307.06,244.14 A05.M2 | v305.79,183.5 304.2,183.5 303.88,183.82 B05.J2 | v304.84,198.11 v308.33,198.11 | v308.33,205.73 308.96,205.09 313.41,205.09 v314.36,206.05 | v313.73,230.18 315.31,231.76 316.58,231.76 321.98,237.16
I/O_INT_RQ\  (via drill 0.61)
  Top 0.254: v367.38,46.03 367.07,46.34 367.07,59.68 368.34,60.95 368.34,73.33 368.65,73.65 368.65,74.6 369.61,75.55 369.61,76.82 368.97,77.46 368.97,98.1 369.61,98.73 369.61,105.08 369.92,105.4 369.92,107.94 370.56,108.57 370.56,111.75 370.24,112.07 370.24,126.35 369.61,126.99 369.61,143.18 370.24,143.81 370.24,148.58 371.51,149.85 v371.51,219.38 | v324.52,219.38 323.89,220.02 323.89,241.61 321.35,244.14 319.76,244.14 A04.M2 | v310.23,201.28 310.23,199.38 312.46,197.15 312.46,194.3 B05.E1 | v311.82,202.55 314.04,202.55 314.04,204.46 315.31,205.73 315.31,219.06 v315,219.38
  Bottom 0.254: v367.38,46.03 367.07,46.03 364.21,43.17 343.57,43.17 343.25,42.85 339.13,42.85 338.81,42.53 320.71,42.53 319.76,41.58 D04.M2 | v371.51,219.38 355,219.38 354.68,219.7 324.84,219.7 v324.52,219.38 v315,219.38 | v310.23,201.28 311.5,202.55 v311.82,202.55
I/O_PWR_CLR  (via drill 0.61)
  Top 0.254: A02.V2 341.35,211.12 340.08,209.86 340.08,151.75 340.4,151.43 340.4,140.64 340.08,140.32 v340.08,121.91 340.08,88.25 341.35,86.98 341.35,72.38 340.08,71.11 340.08,59.36 339.76,59.04 339.76,20.94 341.03,19.67 D02.V2
  Bottom 0.254: v340.08,121.91 315,121.91 313.41,123.49 C05.H1
I/O_SKP_RQ\  (via drill 0.61)
  Top 0.254: v306.74,2.84 306.74,12.69 317.22,23.16 317.22,29.51 320.39,32.69 320.39,35.55 320.08,35.86 320.08,38.72 320.39,39.04 320.39,41.9 319.76,42.53 319.76,46.66 319.44,46.98 D04.K2 | v6.39,7.93 6.7,8.24 6.7,73.33 5.43,74.6 5.43,77.14 6.07,77.77 6.07,177.47 5.43,178.11 5.43,180.64 6.07,181.28 6.07,250.18 4.8,251.45 4.8,266.05 6.07,267.32 v6.07,273.67 | v299.44,291.45 317.22,273.67 317.22,260.97 317.85,260.34 317.85,252.4 318.81,251.45 A04.K2 319.76,250.49 319.76,246.68 327.06,239.38 327.06,234.62 327.38,234.3 327.38,230.81 v328.01,230.18 | v318.49,178.11 317.85,178.74 317.85,194.93 321.98,199.06 321.98,201.6 321.03,202.55 319.12,202.55 319.12,204.46 317.22,206.36 317.22,220.33 v321.35,224.46
  Route2 0.254: v315.63,180.01 316.58,180.01 v318.49,178.11
  Bottom 0.254: v306.74,2.84 306.42,3.16 293.41,3.16 292.14,1.89 265.78,1.89 263.88,3.8 262.29,3.8 261.02,2.53 230.86,2.53 229.59,3.8 226.1,3.8 225.46,4.43 224.83,4.43 224.19,3.8 11.78,3.8 10.51,5.07 9.56,5.07 6.7,7.93 v6.39,7.93 | v6.07,273.67 20.67,288.28 53.69,288.28 54.65,287.32 60.68,287.32 61.31,286.69 83.54,286.69 84.81,287.96 86.71,287.96 87.35,287.32 132.12,287.32 133.7,288.91 142.59,288.91 142.91,288.6 182.92,288.6 184.19,289.86 190.54,289.86 191.17,289.23 207.68,289.23 208.32,289.86 210.86,289.86 211.49,290.5 212.76,290.5 214.03,291.77 216.57,291.77 217.21,291.13 219.11,291.13 219.43,290.82 236.26,290.82 236.89,291.45 269.28,291.45 269.91,292.09 281.66,292.09 282.29,291.45 v299.44,291.45 | v315.63,180.01 314.04,180.01 313.41,180.64 B05.K1 | v321.35,224.46 321.66,224.14 328.01,224.14 330.24,226.36 330.24,230.18 v328.01,230.18
I/O_TS03  (via drill 0.61)
  Top 0.254: v343.89,31.74 343.89,29.51 344.21,29.2 D02.S2 | v301.98,39.99 301.98,43.8 301.66,44.12 301.66,46.34 302.3,46.98 302.3,49.83 301.66,50.47 v301.66,51.74 | v329.92,77.14 329.6,77.46 329.6,86.66 329.92,86.98 329.92,89.84 328.97,90.79 v328.97,91.74 | v326.11,120.32 325.79,120.64 325.79,123.18 C04.H1 | v343.89,228.59 343.89,230.81 344.21,231.13 A02.S2
  Route2 0.254: v316.58,60.31 321.03,64.76 321.03,65.71 322.93,67.61 322.93,68.25 328.97,74.28 328.97,76.19 v329.92,77.14 | v319.44,101.59 321.66,103.81 321.66,106.67 321.03,107.3 321.03,114.92 326.11,120 v326.11,120.32 | v341.98,225.73 341.98,224.78 346.75,220.02 345.16,218.43 345.16,211.44 341.67,207.95 341.67,205.41 340.08,203.82 340.08,199.06 336.59,195.57 336.59,189.22 326.43,179.06 326.43,177.79 v326.11,177.47 | v318.81,159.05 318.81,157.79 v305.79,144.77
  Route15 0.254: v328.97,91.74 328.97,92.06 v319.44,101.59 | v326.11,177.47 319.44,170.8 319.44,170.49 317.54,168.58 317.54,160.33 v318.81,159.05 | v305.79,144.77 304.2,143.18 309.28,138.1 309.6,138.1 311.5,136.2 311.5,135.88 321.66,125.72 323.25,125.72 324.84,124.13 C04.H1
  Bottom 0.254: v343.89,31.74 341.98,33.64 317.85,33.64 312.46,39.04 310.55,39.04 309.6,39.99 v301.98,39.99 | v301.66,51.74 301.66,58.09 302.3,58.09 302.93,58.72 313.41,58.72 315,60.31 v316.58,60.31 | v343.89,228.59 341.98,226.68 v341.98,225.73
I/O_TS04  (via drill 0.61)
  Top 0.254: v303.88,7.29 298.49,1.89 274.99,1.89 274.99,6.66 272.45,9.19 272.45,18.09 272.77,18.4 272.77,22.21 v272.13,22.85 | v252.45,41.58 251.18,42.85 251.18,45.71 251.81,46.34 251.81,49.52 251.18,50.15 251.18,66.03 v252.77,67.61 | v254.67,69.52 254.35,69.84 254.35,72.38 254.04,72.69 254.04,73.33 255.62,74.92 v255.94,74.92 | v301.66,216.21 v301.66,222.24
  Route2 0.254: v272.13,22.85 253.08,41.9 252.77,41.58 v252.45,41.58 | v254.67,69.52 v252.77,67.61 | v255.94,74.92 256.26,74.92 260.07,78.73 260.07,79.68 260.39,80 260.39,96.19 260.7,96.51 260.7,101.91 259.43,103.18 259.43,106.67 263.24,110.48 263.24,114.29 272.13,123.18 273.09,123.18 274.04,122.22 274.36,122.54 281.66,122.54 282.29,123.18 282.29,130.8 v283.25,131.75 | v268.32,134.61 265.15,137.78 266.42,139.05 266.42,141.27 263.88,143.81 263.88,144.45 267.37,147.94 267.37,154.61 265.15,156.83 283.56,175.25 283.56,175.88 281.98,177.47 281.66,177.15 v281.34,177.15 | v269.28,190.49 269.59,190.49 274.04,194.93 274.99,194.93 275.63,195.57 275.63,197.79 278.8,200.96 278.8,202.24 282.61,206.05 282.61,208.9 v280.07,211.44 | v301.66,222.24 301.66,222.55 306.11,227 308.96,227 v309.92,226.05 | v316.58,226.36 317.22,226.36 320.08,229.22 320.71,229.22 v324.84,233.35 | v340.08,233.67 342.94,230.81 341.35,229.22 A02.T2
  Route15 0.254: v281.34,177.15 281.34,177.47 272.13,186.68 272.13,187.63 v269.28,190.49
  Bottom 0.254: v303.88,7.29 360.72,7.29 360.72,16.82 360.08,17.45 353.73,17.45 346.43,24.75 342.3,24.75 341.98,25.07 D02.T2 | v283.25,131.75 282.93,132.07 274.67,132.07 272.13,134.61 v268.32,134.61 | v280.07,211.44 281.66,213.03 298.49,213.03 v301.66,216.21 | v309.92,226.05 310.55,226.68 316.27,226.68 v316.58,226.36 | v324.84,233.35 330.55,233.35 330.87,233.67 334.36,233.67 334.68,233.35 336.9,233.35 337.22,233.67 v340.08,233.67
IM_00\  (via drill 0.61)
  Top 0.254: v365.8,74.92 365.8,145.08 366.43,145.72 v366.43,201.92 | v335.32,200.33 335.32,197.47 B03.D1 | v372.15,266.05 371.83,265.74 371.83,246.37 371.19,245.73 371.19,222.55 v371.51,222.24 | v364.21,221.92 364.53,221.6 364.53,209.22 v363.57,208.27 | v356.27,207.95 355.64,207.31 355.64,204.46 356.91,203.19 v357.22,203.19
  Bottom 0.254: v365.8,74.92 331.19,74.92 327.06,70.79 323.57,70.79 322.93,70.16 D04.B1 | v366.43,201.92 361.03,201.92 360.72,201.6 357.22,201.6 | 357.22,201.6 356.27,201.6 355.95,201.92 342.94,201.92 342.3,201.28 336.27,201.28 v335.32,200.33 | B04.D1 322.93,197.15 323.25,197.47 327.38,197.47 328.01,198.11 332.78,198.11 333.73,197.15 334.36,197.15 B03.D1 | v372.15,266.05 366.75,271.45 324.2,271.45 322.93,272.72 A04.B1 | v371.51,222.24 371.19,221.92 v364.21,221.92 | v363.57,208.27 363.26,208.58 356.91,208.58 v356.27,207.95 | 357.22,201.6 v357.22,203.19
IM_01\  (via drill 0.61)
  Top 0.254: v310.23,5.07 323.89,18.72 323.89,39.68 320.39,43.17 320.39,51.74 320.71,52.06 320.71,57.46 321.98,58.72 321.98,62.85 D04.D1 | v5.12,11.1 5.43,11.42 5.43,72.69 4.16,73.97 4.16,78.41 4.8,79.05 4.8,176.83 4.16,177.47 4.16,181.28 4.8,181.92 4.8,249.54 3.53,250.81 3.53,266.69 4.16,267.32 4.16,287.96 3.53,288.6 v3.53,288.91 | v306.11,290.5 317.85,290.5 317.85,273.04 321.98,268.91 321.98,267.32 A04.D1 | v327.7,194.3 327.38,194.61 327.38,203.82 328.33,204.77 330.24,204.77 330.24,207 v334.05,210.81 | v339.76,210.81 339.44,211.12 339.44,223.83 340.08,224.46 340.08,231.76 342.94,234.62 342.94,260.97 v341.03,262.88
  Bottom 0.254: B04.E1 326.11,193.98 326.43,194.3 v327.7,194.3 330.55,194.3 331.19,194.93 332.78,194.93 334.05,193.66 B03.E1 | v310.23,5.07 308.96,3.8 288.96,3.8 288.33,3.16 266.42,3.16 264.51,5.07 261.66,5.07 260.39,3.8 231.49,3.8 229.59,5.7 224.19,5.7 223.56,5.07 12.42,5.07 9.24,8.24 8.29,8.24 5.43,11.1 v5.12,11.1 | v3.53,288.91 3.53,290.82 52.11,290.82 52.74,290.18 55.6,290.18 56.55,289.23 61.63,289.23 62.27,288.6 82.59,288.6 83.86,289.86 96.56,289.86 97.19,289.23 131.16,289.23 132.75,290.82 143.55,290.82 143.86,290.5 181.96,290.5 183.23,291.77 200.7,291.77 201.33,291.13 206.73,291.13 207.36,291.77 209.9,291.77 211.81,293.68 229.59,293.68 230.54,292.72 235.3,292.72 235.94,293.36 268.32,293.36 268.96,293.99 302.61,293.99 v306.11,290.5 | v339.76,210.81 v334.05,210.81 | v341.03,262.88 338.81,265.1 324.2,265.1 322.93,266.37 A04.D1
IM_02\  (via drill 0.61)
  Top 0.254: v311.5,62.22 311.19,62.53 311.19,67.61 311.82,68.25 311.82,72.06 311.19,72.69 311.19,74.6 311.82,75.24 311.82,83.17 304.52,90.47 304.52,140.96 304.84,141.27 304.84,154.29 304.52,154.61 304.52,177.79 v304.84,178.11 | v329.28,231.76 329.28,232.08 330.24,233.03 330.24,241.61 327.06,244.78 327.06,261.61 325.79,262.88 A04.E1 | v342.94,222.55 343.89,221.6 343.89,213.67 v343.57,213.35 | v330.24,213.35 329.28,212.39 v329.28,205.73 | v326.11,185.73 325.79,185.41 325.79,181.6 B04.K1
  Route2 0.254: v329.28,205.73 334.36,200.65 334.36,199.7 328.01,193.34 328.01,191.76 327.38,191.12 327.38,186.99 v326.11,185.73
  Route15 0.254: v329.28,231.76 329.6,231.76 v334.68,226.68
  Bottom 0.254: v311.5,62.22 312.77,62.22 313.41,61.58 323.89,61.58 324.84,60.63 D04.E1 | v304.84,178.11 305.79,179.06 320.39,179.06 321.98,180.64 324.84,180.64 B04.K1 326.11,180.64 327.06,179.69 332.46,179.69 333.73,180.96 B03.K1 | v334.68,226.68 337.86,223.51 341.98,223.51 v342.94,222.55 | v343.57,213.35 343.25,213.03 330.55,213.03 v330.24,213.35
IM_03\  (via drill 0.61)
  Top 0.254: v316.27,53.64 315.63,53.01 315.63,52.38 314.36,51.1 314.36,46.66 315,46.03 315,45.39 314.36,44.75 314.36,42.53 315,41.9 315,39.04 314.36,38.4 314.36,36.18 315,35.55 315,32.69 314.36,32.06 314.36,21.58 v306.74,13.96 | v219.75,13.01 v222.29,13.01 | v108.94,14.27 108.62,14.59 108.62,21.26 108.3,21.58 108.3,73.97 108.62,74.28 108.62,91.11 108.3,91.43 108.3,163.18 109.89,164.77 v109.89,166.04 | v143.86,168.58 143.23,169.21 143.23,199.06 145.77,201.6 145.77,214.62 146.4,215.25 146.4,251.45 146.72,251.77 146.72,256.21 146.09,256.85 v146.09,295.26 | v204.51,295.58 218.48,295.58 v218.48,281.29 | v236.57,281.29 237.84,282.56 237.84,287.32 237.53,287.64 237.53,288.28 238.16,288.91 239.43,288.91 v239.43,285.1 | v321.98,282.56 323.89,280.66 323.89,267.96 324.2,267.64 324.2,261.29 325.16,260.34 325.16,257.8 A04.H1 | v337.54,179.37 336.9,180.01 336.9,184.46 v337.86,185.41 | v325.79,202.24 324.2,203.82 324.2,208.27 v326.11,210.17 | v349.92,211.76 350.24,212.08 350.24,222.87 v349.92,223.19 | v356.27,223.83 355.95,224.14 355.95,245.73 358.18,247.96 358.18,249.86 358.81,250.49 358.81,252.4 v358.49,252.72
  Route15 0.254: v332.46,191.12 330.55,193.03 330.55,197.47 v325.79,202.24
  Bottom 0.254: B04.L1 322.93,178.11 325.47,178.11 326.43,179.06 330.55,179.06 331.82,177.79 B03.L1 335.63,178.11 336.9,179.37 v337.54,179.37 | v316.27,53.64 317.22,52.69 319.76,52.69 321.03,53.96 D04.H1 | v306.74,13.96 305.79,13.01 292.45,13.01 291.82,12.37 272.13,12.37 271.82,12.05 239.11,12.05 238.16,13.01 233.4,13.01 233.08,12.69 222.6,12.69 v222.29,13.01 | v219.75,13.01 116.24,13.01 115.29,13.96 109.26,13.96 v108.94,14.27 | v109.89,166.04 110.21,166.36 141.64,166.36 v143.86,168.58 | v146.09,295.26 146.4,294.94 172.76,294.94 173.39,295.58 v204.51,295.58 | v218.48,281.29 224.83,281.29 225.14,281.61 232.45,281.61 232.76,281.29 v236.57,281.29 | v239.43,285.1 239.43,284.15 239.75,284.15 241.02,282.88 269.91,282.88 270.86,283.83 299.76,283.83 301.34,282.24 321.66,282.24 v321.98,282.56 | v337.86,185.41 335.32,187.95 334.68,187.95 333.73,188.9 333.73,191.12 v332.46,191.12 | v326.11,210.17 327.7,211.76 v349.92,211.76 | v349.92,223.19 350.56,223.83 v356.27,223.83 | v358.49,252.72 355.64,255.58 337.86,255.58 337.54,255.89 329.6,255.89 328.65,256.85 326.11,256.85 A04.H1
IM_04\  (via drill 0.61)
  Top 0.254: v315,53.64 314.36,54.28 314.36,68.57 314.04,68.88 314.04,72.38 315.31,73.65 315.31,86.66 314.04,87.94 314.04,114.29 310.87,117.46 310.87,148.58 310.55,148.89 310.55,151.43 311.19,152.07 v311.19,159.69 | v311.82,252.4 311.19,251.77 311.19,248.91 311.82,248.27 311.82,245.42 311.19,244.78 311.19,242.56 311.82,241.92 311.82,239.06 311.19,238.43 311.19,236.21 311.82,235.57 311.82,232.71 311.19,232.08 311.19,226.68 310.87,226.36 310.87,215.57 311.19,215.25 311.19,207.95 310.87,207.63 310.87,201.92 311.19,201.6 311.19,199.38 314.04,196.52 314.04,172.39 v313.73,172.07
  Bottom 0.254: v315,53.64 317.85,50.79 D04.J1 | v311.19,159.69 312.14,160.64 314.68,160.64 318.81,164.77 319.12,164.77 | 319.12,164.77 321.66,164.77 B04.R1 322.93,164.77 323.89,163.82 333.41,163.82 334.36,164.77 B03.R1 | v311.82,252.4 316.27,252.4 316.9,253.04 321.03,253.04 321.66,253.67 A04.J1 | v313.73,172.07 313.73,170.17 319.12,164.77
IM_05\  (via drill 0.61)
  Top 0.254: v285.79,37.45 285.47,37.14 285.47,28.56 282.61,25.71 v282.61,15.54 | v256.26,11.1 v260.07,14.91 | v235.94,11.1 234.67,12.37 v234.67,21.58 | v96.24,17.13 94.97,18.4 94.97,82.86 v94.65,83.17 | v99.1,86.66 98.78,86.98 98.78,154.61 99.1,154.93 99.1,157.79 98.78,158.1 98.78,198.74 101,200.96 101,202.24 106.72,207.95 v106.72,210.17 | v109.57,213.03 v109.57,222.24 | v151.48,227 155.29,227 155.29,266.69 v158.15,269.55 | v188,270.81 190.54,270.81 v190.54,272.72 | v221.02,274.62 222.6,276.21 222.6,279.07 225.14,281.61 228.95,281.61 v228.95,278.12 | v321.03,287.01 321.03,270.81 323.25,268.59 323.25,267.64 323.57,267.32 323.57,260.97 323.89,260.66 323.89,249.54 322.62,248.27 A04.L1 | v338.81,166.04 337.86,165.09 337.86,162.55 B03.S1 | v349.92,176.52 350.24,176.83 v350.24,179.37 | v363.57,210.17 363.26,210.49 363.26,222.24 v364.21,223.19 | v368.97,241.29 v368.97,230.18 | v365.48,249.54 365.16,249.86 v365.16,284.79
  Route2 0.254: v338.81,166.04 339.44,166.04 v347.06,173.66 | v355.64,200.96 356.27,200.96 358.18,202.87 358.18,203.82 361.35,207 361.35,207.95 v363.57,210.17
  Route15 0.254: v228.95,278.12 232.45,281.61 232.76,281.29 234.35,281.29 v241.02,287.96 | v356.91,195.57 v353.73,192.39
